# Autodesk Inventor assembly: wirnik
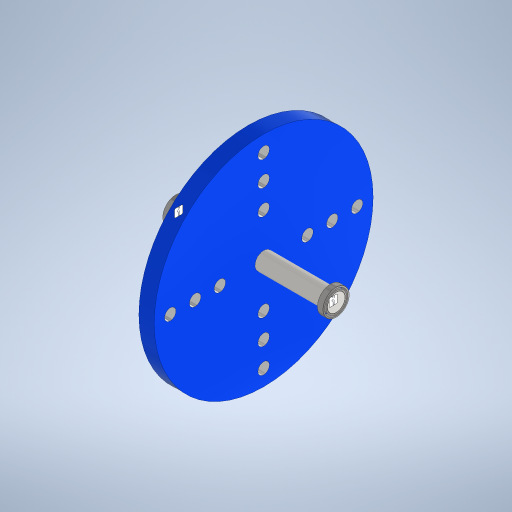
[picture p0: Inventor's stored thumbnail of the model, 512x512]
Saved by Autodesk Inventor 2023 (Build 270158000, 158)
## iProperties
Created: 2023-02
Part Number: wirnik
Document SubType Name: Assembly
Designer: Admin
Author: Admin
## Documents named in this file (4)
- C:\Users\Admin\Desktop\DYNAMIKA MASZYN zmiany\nowe laboratorium mechatronika 2021\nowe lab04 - drgania swobodne\wał_i_krazek\wirnik.iam
- C:\Users\Admin\Desktop\DYNAMIKA MASZYN zmiany\nowe laboratorium mechatronika 2021\nowe lab04 - drgania swobodne\wał_i_krazek\shaft.ipt
- C:\Users\Admin\Desktop\DYNAMIKA MASZYN zmiany\nowe laboratorium mechatronika 2021\nowe lab04 - drgania swobodne\wał_i_krazek\disk.ipt
- C:\Users\Admin\Documents\Inventor\Content Center Files\R2023\pl-PL\UNI ISO 15\ISO 15 - 7 17 12 x 18 x 4.ipt
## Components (4 placed, 3 different names)
1. shaft:1 — Zestawiające:1, Równoległe:1, Zestawiające:2, Równoległe:2, Zestawiające:3, Równoległe:3
2. disk:1 — Zestawiające:1, Równoległe:1
3. UNI ISO 15 7 17 12 x 18 x 4:1 — Zestawiające:2, Równoległe:2
4. UNI ISO 15 7 17 12 x 18 x 4:2 — Zestawiające:3, Równoległe:3
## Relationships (6: Mate 3, Flush 3)
- Zestawiające:1 [Mate]: shaft:1 ↔ disk:1
- Równoległe:1 [Flush]: shaft:1 ↔ disk:1
- Zestawiające:2 [Mate]: shaft:1 ↔ UNI ISO 15 7 17 12 x 18 x 4:1
- Równoległe:2 [Flush]: shaft:1 ↔ UNI ISO 15 7 17 12 x 18 x 4:1
- Zestawiające:3 [Mate]: shaft:1 ↔ UNI ISO 15 7 17 12 x 18 x 4:2
- Równoległe:3 [Flush]: shaft:1 ↔ UNI ISO 15 7 17 12 x 18 x 4:2
## Named parameters: sa_0 = 8000000 mm, sa_1 = 1e+10 mm, sa_2 = 8000000 mm, sa_3 = 1e+10 mm
